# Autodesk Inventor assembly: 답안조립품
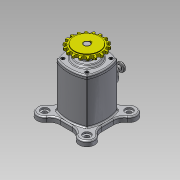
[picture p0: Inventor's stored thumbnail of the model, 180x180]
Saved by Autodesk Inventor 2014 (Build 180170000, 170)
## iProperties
Created: 2016-05
Part Number: 답안조립품
Document SubType Name: Assembly
Designer: S.Y.PARK
Author: S.Y.PARK
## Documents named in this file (11)
- C:\Users\Administrator\Desktop\460507V1020\답안조립품.iam
- C:\Users\Administrator\Desktop\460507V1020\1-본체.ipt
- C:\Users\Administrator\Desktop\460507V1020\M4x0.7x12.ipt
- C:\Users\Administrator\Desktop\460507V1020\베어링-6203.ipt
- C:\Users\Administrator\Desktop\460507V1020\부시.ipt
- C:\Users\Administrator\Desktop\460507V1020\스프로킷.ipt
- C:\Users\Administrator\Desktop\460507V1020\슬라이더.ipt
- C:\Users\Administrator\Desktop\460507V1020\오일실.ipt
- C:\Users\Administrator\Desktop\460507V1020\커버.ipt
- C:\Users\Administrator\Desktop\460507V1020\키5x5.ipt
- C:\Users\Administrator\Desktop\460507V1020\편심축.ipt
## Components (9 placed, 2 different names)
1. 1-본체:1
2. M4x0.7x12:1
3. M4x0.7x12:3
4. M4x0.7x12:4
5. M4x0.7x12:5
6. M4x0.7x12:2
7. M4x0.7x12:6
8. M4x0.7x12:7
9. M4x0.7x12:8
